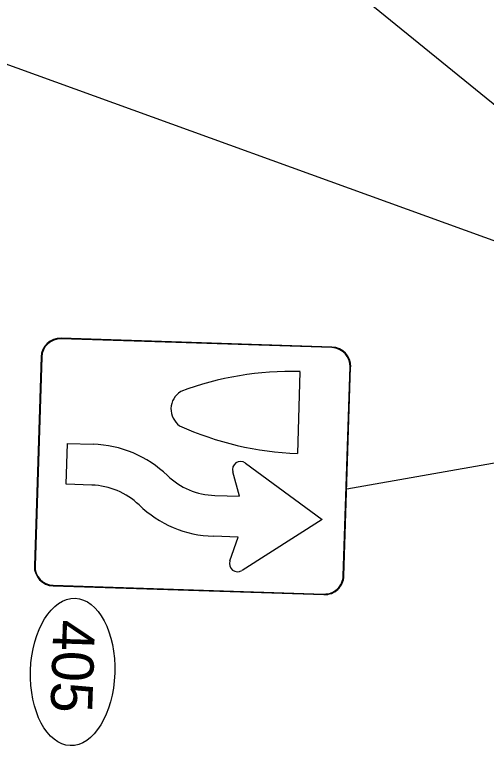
# Model space of a CAD drawing. Extents: x 2096670 to 2098561, y 684033 to 689893.
# Drawn here: x 2097265.5 to 2097401.3, y 686741.2 to 686951.8 of the extents above; entities that cross this region are included whole.
import ezdxf

# ---------------------------------------------------------------- set-up
doc = ezdxf.new("R2010")
doc.units = 0
for name, color, linetype in [('Exist Sign E Speed Limit XX CELL', 7, 'Continuous'), ('Prop Sign E Keep Right CELL', 7, 'Continuous'), ('Prop Sign E One Way_Right CELL', 7, 'Continuous'), ('Prop Sign E Stop Sign Ahead CELL', 7, 'Continuous')]:
    doc.layers.add(name, color=color, linetype=linetype)

# ---------------------------------------------------------------- blocks, each defined once
blk = doc.blocks.new('R4_7A')
at = {"layer": 'Prop Sign E Keep Right CELL'}
blk.add_line((0.563, 6.375), (2.563, 6.375), dxfattribs=at)
blk.add_line((0.563, 6.375), (2.563, 6.375), dxfattribs=at)
blk.add_line((0.563, 6.375), (2.563, 6.375), dxfattribs=at)
for points in [[(2.841, 5.115), (4.156, 7.031), (5.471, 5.115)], [(2.841, 5.115), (4.156, 7.031), (5.471, 5.115)], [(2.841, 5.115), (4.156, 7.031), (5.471, 5.115)], [(3.656, 4.387), (3.656, 4.998), (3.067, 4.811)], [(3.656, 4.387), (3.656, 4.998), (3.067, 4.811)], [(3.656, 4.387), (3.656, 4.998), (3.067, 4.811)], [(5.246, 4.811), (4.656, 4.998), (4.656, 4.387)], [(5.246, 4.811), (4.656, 4.998), (4.656, 4.387)], [(5.246, 4.811), (4.656, 4.998), (4.656, 4.387)], [(3.5, 1.375), (3.5, 0.75), (2.5, 0.75), (2.5, 1.375)], [(3.5, 1.375), (3.5, 0.75), (2.5, 0.75), (2.5, 1.375)], [(3.5, 1.375), (3.5, 0.75), (2.5, 0.75), (2.5, 1.375)]]:
    blk.add_lwpolyline(points, dxfattribs=at)
for centre, radius, start, end in [((8.062, 6.373), 7.5, 179.9823, 202.7267), ((8.062, 6.373), 7.5, 179.9823, 202.7267), ((8.062, 6.373), 7.5, 179.9823, 202.7267), ((-4.938, 6.373), 7.5, 337.2733, 0.0177), ((-4.938, 6.373), 7.5, 337.2733, 0.0177), ((-4.938, 6.373), 7.5, 337.2733, 0.0177), ((3.006, 5.001), 0.2, 145.5508, 287.601), ((3.006, 5.001), 0.2, 145.5508, 287.601), ((3.006, 5.001), 0.2, 145.5508, 287.601), ((5.306, 5.001), 0.2, 252.399, 34.4492), ((5.306, 5.001), 0.2, 252.399, 34.4492), ((5.306, 5.001), 0.2, 252.399, 34.4492), ((1.906, 4.387), 1.75, 317.9924, 0), ((1.906, 4.387), 1.75, 317.9924, 0), ((1.906, 4.387), 1.75, 317.9924, 0), ((1.906, 4.387), 2.75, 317.9924, 0), ((1.906, 4.387), 2.75, 317.9924, 0), ((1.906, 4.387), 2.75, 317.9924, 0), ((1.562, 3.75), 0.5, 213.3458, 326.6542), ((1.562, 3.75), 0.5, 213.3458, 326.6542), ((1.562, 3.75), 0.5, 213.3458, 326.6542), ((5.25, 1.375), 2.75, 137.9924, 180), ((5.25, 1.375), 2.75, 137.9924, 180), ((5.25, 1.375), 2.75, 137.9924, 180), ((5.25, 1.375), 1.75, 137.9924, 180), ((5.25, 1.375), 1.75, 137.9924, 180), ((5.25, 1.375), 1.75, 137.9924, 180)]:
    blk.add_arc(centre, radius, start, end, dxfattribs=at)

msp = doc.modelspace()

# ---------------------------------------------------------------- linework, layer by layer
at = {"layer": 'Exist Sign E Speed Limit XX CELL'}
msp.add_line((2097487.09, 686857.91), (2097316.08, 686996.98), dxfattribs=at)
at = {"layer": 'Prop Sign E Keep Right CELL'}
for p, q in [((2097356.83, 686856.11), (2097278.86, 686858.63)), ((2097356.82, 686855.93), (2097278.86, 686858.44)), ((2097273.11, 686853.24), (2097271.17, 686793.1)), ((2097273.3, 686853.23), (2097271.36, 686793.09)), ((2097273.11, 686853.24), (2097273.3, 686853.23)), ((2097273.11, 686853.24), (2097273.3, 686853.23)), ((2097360.08, 686790.22), (2097362.03, 686850.37)), ((2097360.27, 686790.22), (2097362.21, 686850.36)), ((2097276.56, 686787.35), (2097354.52, 686784.83)), ((2097276.57, 686787.53), (2097354.53, 686785.01))]:
    msp.add_line(p, q, dxfattribs=at)
for centre, radius, start, end in [((2097278.68, 686853.06), 5.57, 88.1495, 178.1495), ((2097278.68, 686853.06), 5.39, 88.1495, 178.1495), ((2097356.65, 686850.54), 5.39, 358.1495, 88.1495), ((2097356.65, 686850.54), 5.57, 358.1495, 88.1495), ((2097276.74, 686792.92), 5.57, 178.1495, 268.1495), ((2097276.74, 686792.92), 5.39, 178.1495, 268.1495), ((2097354.7, 686790.4), 5.57, 268.1495, 358.1495), ((2097354.7, 686790.4), 5.39, 268.1495, 358.1495)]:
    msp.add_arc(centre, radius, start, end, dxfattribs=at)
at = {"layer": 'Prop Sign E One Way_Right CELL'}
msp.add_line((2097361.08, 686815.27), (2097674.44, 686870.42), dxfattribs=at)
msp.add_ellipse((2097282.18, 686762.59), major_axis=(0.7, 21.21), ratio=0.571429, dxfattribs=at)
at = {"layer": 'Prop Sign E Stop Sign Ahead CELL'}
msp.add_line((2097236.72, 686947.14), (2097477.76, 686859.77), dxfattribs=at)

# ---------------------------------------------------------------- block references
at = {"layer": 'Prop Sign E Keep Right CELL', "xscale": 11.767345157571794, "yscale": 11.767345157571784, "rotation": -91.8504671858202}
msp.add_blockref('R4_7A', (2097272.86, 686858.06), dxfattribs=at)

# ---------------------------------------------------------------- texts
at = {"layer": 'Prop Sign E One Way_Right CELL'}
msp.add_text('405', height=11.98, rotation=268.1155, dxfattribs=at).set_placement((2097276.69, 686777.74))

doc.saveas('drawing.dxf')
